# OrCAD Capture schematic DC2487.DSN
size A; title: LT6363 Driver Board; rev: 0; note: DC2487A
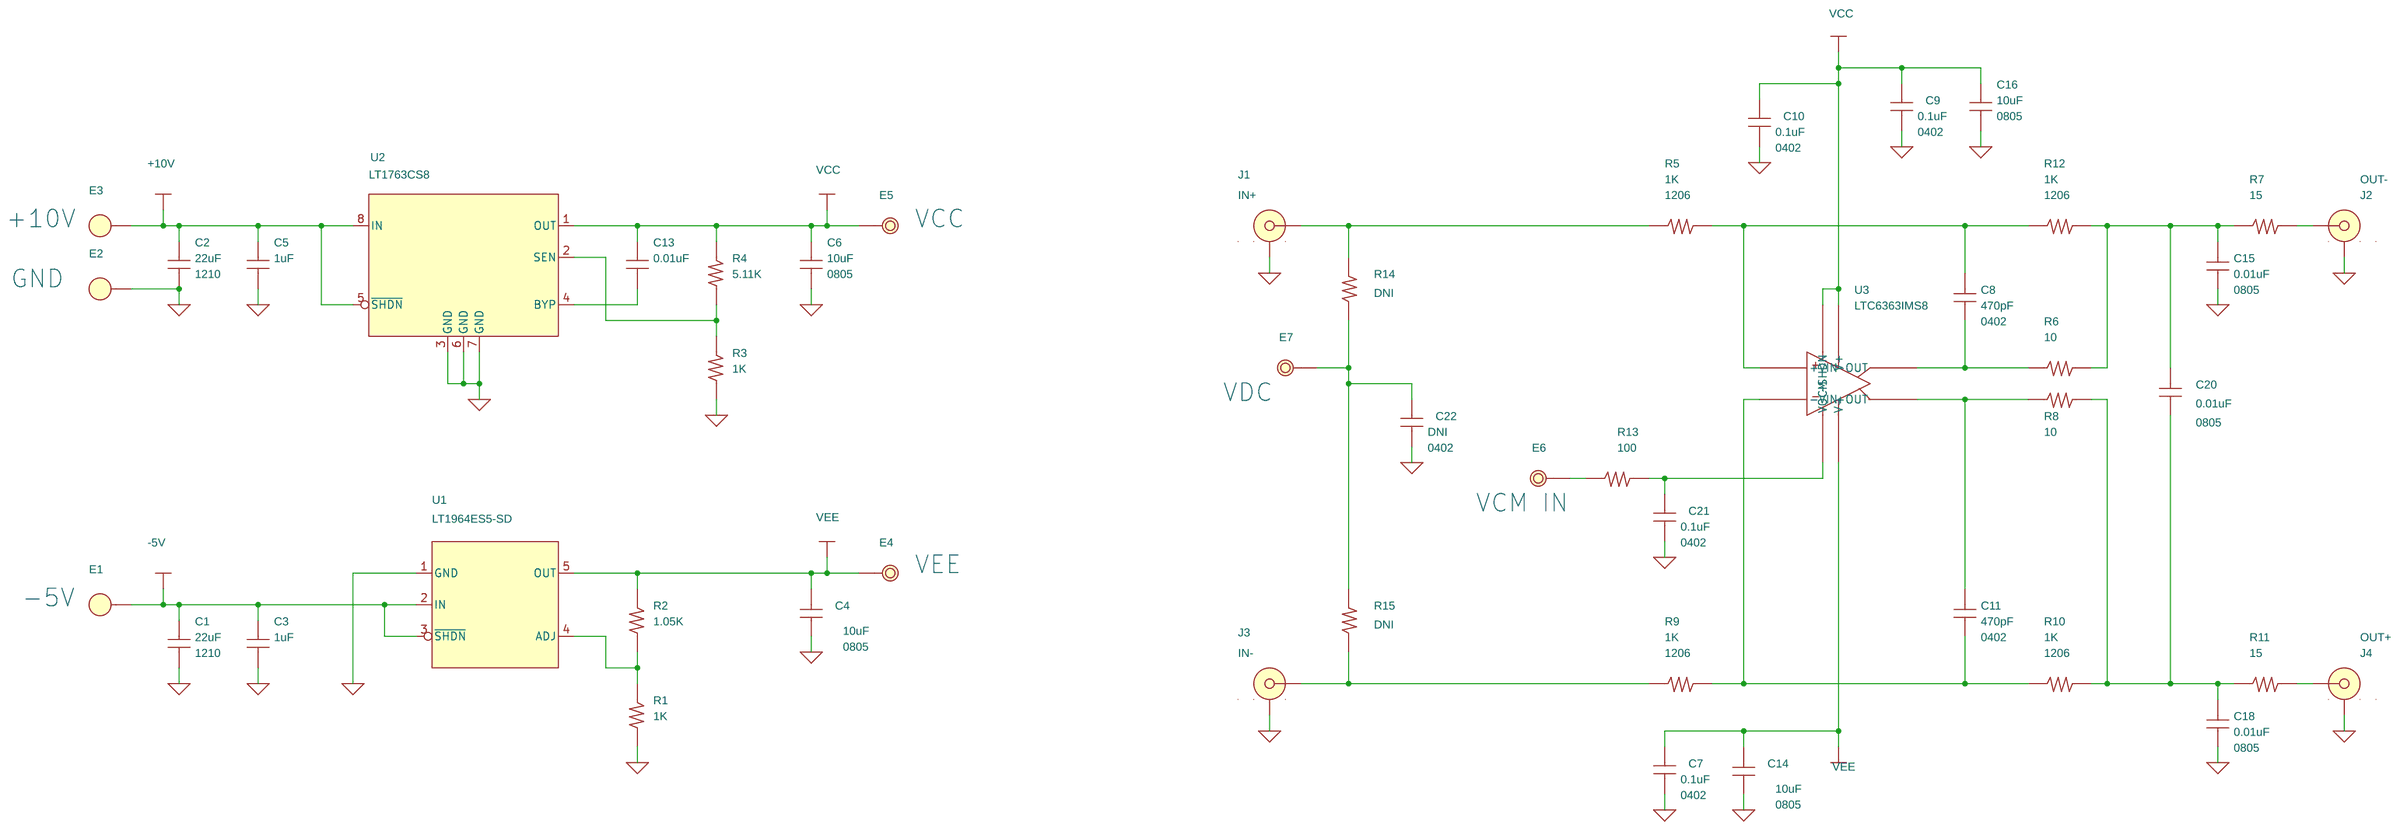
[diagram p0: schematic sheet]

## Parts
C1  22uF  [1210]
C2  22uF  [1210]
C3  1uF  [0603]
C4  10uF  [0805]
C5  1uF  [0603]
C6  10uF  [0805]
C7  0.1uF  [0402]
C8  470pF  [0402]
C9  0.1uF  [0402]
C10  0.1uF  [0402]
C11  470pF  [0402]
C13  0.01uF  [0603]
C14  10uF  [0805]
C15  0.01uF  [0805]
C16  10uF  [0805]
C18  0.01uF  [0805]
C20  0.01uF  [0805]
C21  0.1uF  [0402]
C22  DNI  [0402]
E1  MIL-MAX-2501  [MILL-MAX-2501]
E2  MIL-MAX-2501  [MILL-MAX-2501]
E3  MIL-MAX-2501  [MILL-MAX-2501]
E4  MILL-MAX-2308  [MILL-MAX-2308]
E5  MILL-MAX-2308  [MILL-MAX-2308]
E6  MILL-MAX-2308  [MILL-MAX-2308]
E7  MILL-MAX-2308  [MILL-MAX-2308]
J1  CON-SMA-R-6LAYERS  [EFJOHNSON142-0701-851]
J2  CON-SMA-R-6LAYERS  [EFJOHNSON142-0701-851]
J3  CON-SMA-R-6LAYERS  [EFJOHNSON142-0701-851]
J4  CON-SMA-R-6LAYERS  [EFJOHNSON142-0701-851]
R1  1K  [0603]
R2  1.05K  [0603]
R3  1K  [0603]
R4  5.11K  [0603]
R5  1K  [1206]
R6  10  [0603]
R7  15  [0603]
R8  10  [0603]
R9  1K  [1206]
R10  1K  [1206]
R11  15  [0603]
R12  1K  [1206]
R13  100  [0603]
R14  DNI  [0603]
R15  DNI  [0603]
U1  LT1964ES5-SD  [SOT23-S5]
U2  LT1763CS8  [SO8]
U3  LTC6363IMS8

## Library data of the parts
C1-C3 C5 = CAP-NP: 1ST PART FIELD: 16V
C4 C6-C11 C13-C16 C18 C20-C22 = CAP-NP
E1-E3 = E-094
E4-E7 = E-064
J1 = CON_SMA-END_3: CONN, BNC, SMA 50-OHM EDGE-LANCH; Part Number: E.F.JOHNSON, 142-0701-851; label: IN+
J2 = CON_SMA-END_3: CONN, BNC, SMA 50-OHM EDGE-LANCH; Part Number: E.F.JOHNSON, 142-0701-851; label: OUT-
J3 = CON_SMA-END_3: CONN, BNC, SMA 50-OHM EDGE-LANCH; Part Number: E.F.JOHNSON, 142-0701-851; label: IN-
J4 = CON_SMA-END_3: CONN, BNC, SMA 50-OHM EDGE-LANCH; Part Number: E.F.JOHNSON, 142-0701-851; label: OUT+
R1-R15 = R
U1 = LT1964ES5-SD-SOT23-5
U2 = LT1763CS8-SO8
U3 = AD9685BD_1

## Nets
+10V: C2.1 C5.1 E3.1(A) U2.5(~{SHDN}) U2.8(IN)
-5V: C1.1 C3.1 E1.1(A) U1.2(IN) U1.3(~{SHDN})
GND: C1.2 C2.2 C3.2 C4.1 C5.2 C6.2 C7.2 C9.2 C10.2 C14.1 C15.1 C16.2 C18.1 C21.2 C22.2 E2.1(A) J1.4(GND) J2.4(GND) J3.4(GND) J4.4(GND) R1.2 R3.2 U1.1(GND) U2.3(GND) U2.6(GND) U2.7(GND)
SGND: J1.2(SGND) J1.3(SGND) J1.5(SGND) J2.2(SGND) J2.3(SGND) J2.5(SGND) J3.2(SGND) J3.3(SGND) J3.5(SGND) J4.2(SGND) J4.3(SGND) J4.5(SGND)
VCC: C6.1 C9.1 C10.1 C13.1 C16.1 E5.1(A) R4.1 U2.1(OUT) U3.3(V+) U3.7(~SHDN)
VEE: C4.2 C7.1 C14.2 E4.1(A) R2.1 U1.5(OUT) U3.6(V-)
N4126329: R3.1 R4.2 U2.2(SEN)
N4126471: C13.2 U2.4(BYP)
N6225841: R1.1 R2.2 U1.4(ADJ)
N6228947: C8.2 R5.2 R12.1 U3.8(+VIN)
N6229037: J1.1(CENTER) R5.1 R14.2
N6231223: C18.2 C20.1 R8.2 R10.2 R11.1
N6232016: J2.1(CENTER) R7.2
N6232028: C15.2 C20.2 R6.2 R7.1 R12.2
N6232184: J3.1(CENTER) R9.1 R15.1
N6367911: J4.1(CENTER) R11.2
N6381033: C11.1 R9.2 R10.1 U3.1(-VIN)
N6385335: C8.1 R6.1 U3.5(-OUT)
N6385471: C11.2 R8.1 U3.4(+OUT)
N6396508: C21.1 R13.2 U3.2(VOCM)
N6399369: E6.1(A) R13.1
N6425389: C22.1 E7.1(A) R14.1 R15.2

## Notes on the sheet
- +10V
- VCC
- GND
- VDC
- VCM IN
- VEE
- -5V
